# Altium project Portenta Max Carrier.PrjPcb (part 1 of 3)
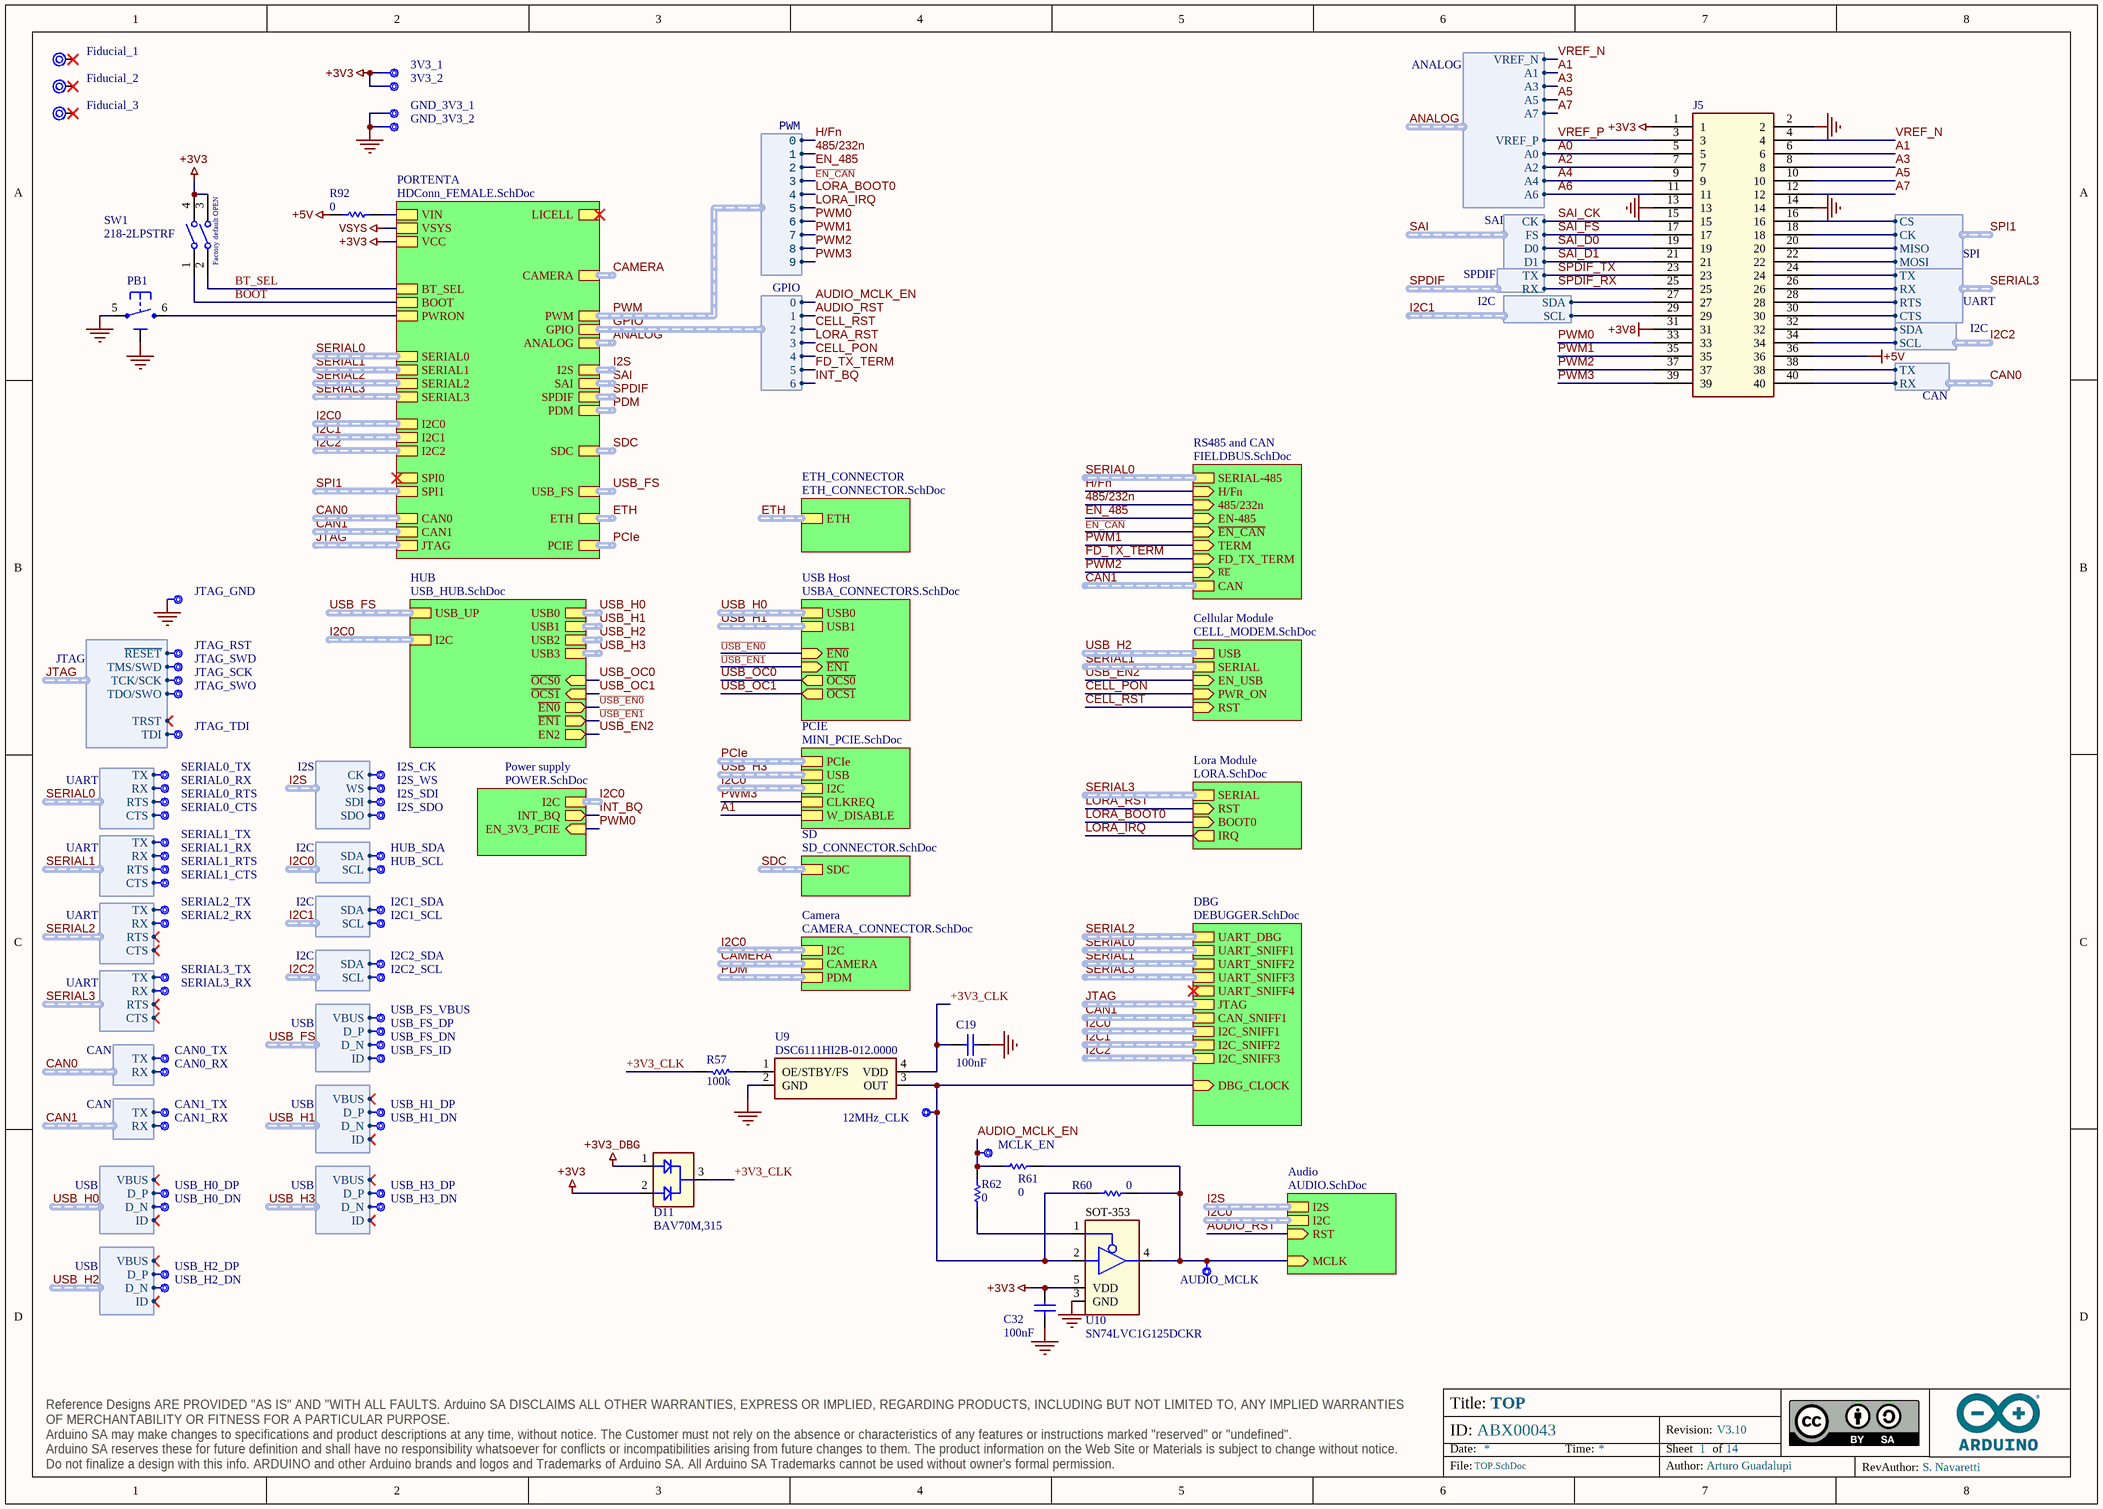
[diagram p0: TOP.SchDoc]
THICKNESS: 1.6mm; THD: X; TBD: _; TABS: X; SOLDERMASK_TOP: X; SOLDERMASK_PEELABLE_TOP: _; SOLDERMASK_PEELABLE_COLOR: _; SOLDERMASK_PEELABLE_BOTTOM: _; SOLDERMASK_COLOR: BLACK; SOLDERMASK_BOTTOM: X; SN/PB: _; SMD: X; SKU: ABX00043; SILK_TOP: X; SILK_COLOR: WHITE; SILK_BOTTOM: X; SCORING: _; RIGID/FLEX: _; RIGID: X; Revision: V3.10; PRESSFIT: _; POLYMIDE: _; PCB_SIZE: 101.60 mm x 101.60 mm; PANEL_SIZE: 230.20 mm x 120.60 mm; PANEL_REQUESTED: _; PANEL_PROVIDED: X; PANEL_NO: _; N_FIGURES: 2; NLAYERS: 4; NI/AU: _; MIN_TRACK_WIDTH_OUTER: 0.15mm; MIN_TRACK_WIDTH_INNER: 0.15mm; MIN_INSULATION_OUTER: 0.15mm; MIN_INSULATION_INNER: 0.15mm; MILLING: X; IPCNA: X; IPC3: _; IPC2: _; IPC1: _; HOLE_TOP_BOTTOM: X; HAL_LF: _; HAL: _; FR4_HTG: _; FR4: X; FLEX: _; FINISH_TBD: _; ENIG: X; EDGE_PLATING: _; DRILLS_SOLDER_FILLING: X; DRILLS_SLOT: _; DRILLS_RESIN_FILLING: _; DRILLS_PRESSFIT: _; DRILLS_LASER: _; DRILLS_FULL: X; DRILLS_COPPER_FILLING: _; DRILLS_BURIED: _; DRILLS_BLIND: _; BGA: _; Author: Silvio Navaretti; ADJUSTMENTS: _
14 sheets, 504 parts. Net scope: hierarchical (ports join the sheet entries above them; power ports are global).
Board files: PCB.PcbDoc, Panel.PcbDoc
Sheets:
  TOP.SchDoc
    Power supply = POWER.SchDoc
    RS485 and CAN = FIELDBUS.SchDoc
    PORTENTA = HDConn_FEMALE.SchDoc
    Audio = AUDIO.SchDoc
    PCIE = MINI_PCIE.SchDoc
    SD = SD_CONNECTOR.SchDoc
    Cellular Module = CELL_MODEM.SchDoc
    HUB = USB_HUB.SchDoc
    USB Host = USBA_CONNECTORS.SchDoc
    Camera = CAMERA_CONNECTOR.SchDoc
    Lora Module = LORA.SchDoc
    DBG = DEBUGGER.SchDoc
    ETH_CONNECTOR = ETH_CONNECTOR.SchDoc

## Sheet TOP.SchDoc: TOP
size A3; Author: Arturo Guadalupi; CompanyName: Arduino srl; DocumentNumber: ABX00043; Revision: V3.10; SheetNumber: 1; SheetTotal: 14; RevAuthor: S. Navaretti; Number: HWECB-42

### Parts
3V3_1  CMP-018-0005-A.3  [TP-1.00MM]  (value not drawn)  (no BOM)
3V3_2  CMP-018-0005-A.3  [TP-1.00MM]  (value not drawn)  (no BOM)
12MHz_CLK  CMP-018-0005-A.3  [TP-1.00MM]  (value not drawn)  (no BOM)
AUDIO_MCLK  CMP-018-0005-A.3  [TP-1.00MM]  (value not drawn)  (no BOM)
C19  value 100nF  [CAP-0402]  (hidden comment: C0402C104K4RACTU)
C32  value 100nF  [CAP-0402]  (hidden comment: C0402C104K4RACTU)
CAN0_RX  CMP-018-0005-A.3  [TP-1.00MM]  (value not drawn)  (no BOM)
CAN0_TX  CMP-018-0005-A.3  [TP-1.00MM]  (value not drawn)  (no BOM)
CAN1_RX  CMP-018-0005-A.3  [TP-1.00MM]  (value not drawn)  (no BOM)
CAN1_TX  CMP-018-0005-A.3  [TP-1.00MM]  (value not drawn)  (no BOM)
D11  BAV70M,315  [SOT883]
Fiducial_1  Fiducial mark 1mm with 2mm solder  [Fiducial mark 1mm with circle-Footprint-1]  (value not drawn)  (no BOM)
Fiducial_2  Fiducial mark 1mm with 2mm solder  [Fiducial mark 1mm with circle-Footprint-1]  (value not drawn)  (no BOM)
Fiducial_3  Fiducial mark 1mm with 2mm solder  [Fiducial mark 1mm with circle-Footprint-1]  (value not drawn)  (no BOM)
GND_3V3_1  CMP-018-0005-A.3  [TP-1.00MM]  (value not drawn)  (no BOM)
GND_3V3_2  CMP-018-0005-A.3  [TP-1.00MM]  (value not drawn)  (no BOM)
HUB_SCL  CMP-018-0005-A.3  [TP-1.00MM]  (value not drawn)  (no BOM)
HUB_SDA  CMP-018-0005-A.3  [TP-1.00MM]  (value not drawn)  (no BOM)
I2C1_SCL  CMP-018-0005-A.3  [TP-1.00MM]  (value not drawn)  (no BOM)
I2C1_SDA  CMP-018-0005-A.3  [TP-1.00MM]  (value not drawn)  (no BOM)
I2C2_SCL  CMP-018-0005-A.3  [TP-1.00MM]  (value not drawn)  (no BOM)
I2C2_SDA  CMP-018-0005-A.3  [TP-1.00MM]  (value not drawn)  (no BOM)
I2S_CK  CMP-018-0005-A.3  [TP-1.00MM]  (value not drawn)  (no BOM)
I2S_SDI  CMP-018-0005-A.3  [TP-1.00MM]  (value not drawn)  (no BOM)
I2S_SDO  CMP-018-0005-A.3  [TP-1.00MM]  (value not drawn)  (no BOM)
I2S_WS  CMP-018-0005-A.3  [TP-1.00MM]  (value not drawn)  (no BOM)
J5  FW-20-05-G-D-254-150  [FW-20-05-G-D-254-150-Footprint-1]  (value not drawn)
JTAG_GND  CMP-018-0005-A.3  [TP-1.00MM]  (value not drawn)  (no BOM)
JTAG_RST  CMP-018-0005-A.3  [TP-1.00MM]  (value not drawn)  (no BOM)
JTAG_SCK  CMP-018-0005-A.3  [TP-1.00MM]  (value not drawn)  (no BOM)
JTAG_SWD  CMP-018-0005-A.3  [TP-1.00MM]  (value not drawn)  (no BOM)
JTAG_SWO  CMP-018-0005-A.3  [TP-1.00MM]  (value not drawn)  (no BOM)
JTAG_TDI  CMP-018-0005-A.3  [TP-1.00MM]  (value not drawn)  (no BOM)
MCLK_EN  CMP-018-0005-A.3  [TP-1.00MM]  (value not drawn)  (no BOM)
PB1  PTS820J25KSMTRLFS  [C&K_PTS820_NO_HOLES-1]  (value not drawn)
R57  value 100k  [RES-0402]  (hidden comment: CRCW0402100KFKEDC)
R60  value 0  [RES-0402]  (hidden comment: CRCW04020000Z0EDC)
R61  value 0  [RES-0402]  (hidden comment: CRCW04020000Z0EDC)
R62  value 0  [RES-0402]  (hidden comment: CRCW04020000Z0EDC)
R92  value 0  [RES-0805]  (hidden comment: CRCW08050000Z0EB)
SERIAL0_CTS  CMP-018-0005-A.3  [TP-1.00MM]  (value not drawn)  (no BOM)
SERIAL0_RTS  CMP-018-0005-A.3  [TP-1.00MM]  (value not drawn)  (no BOM)
SERIAL0_RX  CMP-018-0005-A.3  [TP-1.00MM]  (value not drawn)  (no BOM)
SERIAL0_TX  CMP-018-0005-A.3  [TP-1.00MM]  (value not drawn)  (no BOM)
SERIAL1_CTS  CMP-018-0005-A.3  [TP-1.00MM]  (value not drawn)  (no BOM)
SERIAL1_RTS  CMP-018-0005-A.3  [TP-1.00MM]  (value not drawn)  (no BOM)
SERIAL1_RX  CMP-018-0005-A.3  [TP-1.00MM]  (value not drawn)  (no BOM)
SERIAL1_TX  CMP-018-0005-A.3  [TP-1.00MM]  (value not drawn)  (no BOM)
SERIAL2_RX  CMP-018-0005-A.3  [TP-1.00MM]  (value not drawn)  (no BOM)
SERIAL2_TX  CMP-018-0005-A.3  [TP-1.00MM]  (value not drawn)  (no BOM)
SERIAL3_RX  CMP-018-0005-A.3  [TP-1.00MM]  (value not drawn)  (no BOM)
SERIAL3_TX  CMP-018-0005-A.3  [TP-1.00MM]  (value not drawn)  (no BOM)
SW1  218-2LPSTRF  [CTS-218-2LPST_V]
U9  DSC6111HI2B-012.0000  [DFN120P120X89-4M]
U10  SN74LVC1G125DCKR  [SC70-5]
USB_FS_DN  CMP-018-0005-A.3  [TP-1.00MM]  (value not drawn)  (no BOM)
USB_FS_DP  CMP-018-0005-A.3  [TP-1.00MM]  (value not drawn)  (no BOM)
USB_FS_ID  CMP-018-0005-A.3  [TP-1.00MM]  (value not drawn)  (no BOM)
USB_FS_VBUS  CMP-018-0005-A.3  [TP-1.00MM]  (value not drawn)  (no BOM)
USB_H0_DN  CMP-018-0005-A.3  [TP-1.00MM]  (value not drawn)  (no BOM)
USB_H0_DP  CMP-018-0005-A.3  [TP-1.00MM]  (value not drawn)  (no BOM)
USB_H1_DN  CMP-018-0005-A.3  [TP-1.00MM]  (value not drawn)  (no BOM)
USB_H1_DP  CMP-018-0005-A.3  [TP-1.00MM]  (value not drawn)  (no BOM)
USB_H2_DN  CMP-018-0005-A.3  [TP-1.00MM]  (value not drawn)  (no BOM)
USB_H2_DP  CMP-018-0005-A.3  [TP-1.00MM]  (value not drawn)  (no BOM)
USB_H3_DN  CMP-018-0005-A.3  [TP-1.00MM]  (value not drawn)  (no BOM)
USB_H3_DP  CMP-018-0005-A.3  [TP-1.00MM]  (value not drawn)  (no BOM)

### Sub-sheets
Audio = AUDIO.SchDoc: RST (in), I2C (harness I2C), I2S (harness I2S), MCLK (in)
Camera = CAMERA_CONNECTOR.SchDoc: CAMERA (harness CAMERA), I2C (harness I2C), PDM (harness PDM)
Cellular Module = CELL_MODEM.SchDoc: USB (harness USB), EN_USB (in), PWR_ON (in), RST (in), SERIAL (harness SERIAL)
DBG = DEBUGGER.SchDoc: JTAG (harness JTAG), UART_SNIFF4 (harness UART), UART_SNIFF2 (harness UART), UART_SNIFF3 (harness UART), UART_SNIFF1 (harness UART), CAN_SNIFF1 (harness CAN), I2C_SNIFF1 (harness I2C), I2C_SNIFF3 (harness I2C), I2C_SNIFF2 (harness I2C), UART_DBG (harness UART), DBG_CLOCK (in)
ETH_CONNECTOR = ETH_CONNECTOR.SchDoc: ETH (harness ETH)
HUB = USB_HUB.SchDoc: USB0 (harness USB), USB1 (harness USB), USB2 (harness USB), USB3 (harness USB), USB_UP (harness USB), I2C (harness I2C), ~{OCS1} (in), ~{OCS0} (in), ~{EN0} (out), ~{EN1} (out), EN2 (out)
Lora Module = LORA.SchDoc: RST (in), BOOT0 (in), IRQ (out), SERIAL (harness UART)
PCIE = MINI_PCIE.SchDoc: PCIe (harness PCIE), USB (harness USB), I2C (harness I2C), CLKREQ, W_DISABLE
PORTENTA = HDConn_FEMALE.SchDoc: PWRON, PWM (harness PWM), GPIO (harness GPIO), CAMERA (harness CAMERA), I2S (harness I2S), SERIAL0 (harness UART), SPDIF (harness SPDIF), CAN1 (harness CAN), PDM (harness PDM), I2C1 (harness I2C), CAN0 (harness CAN), SERIAL1 (harness UART), I2C0 (harness I2C), SDC (harness SDC), ETH (harness ETH), BT_SEL, SPI1 (harness SPI), SPI0 (harness SPI), SERIAL2 (harness UART), SERIAL3 (harness UART), SAI (harness SAI), BOOT, I2C2 (harness I2C), PCIE (harness PCIE), ANALOG (harness ANALOG), USB_FS (harness USB), JTAG (harness JTAG), VCC, LICELL, VIN, VSYS
Power supply = POWER.SchDoc: I2C (harness I2C), INT_BQ (out), EN_3V3_PCIE (in)
RS485 and CAN = FIELDBUS.SchDoc: H/Fn (in), 485/232n (in), SERIAL-485 (harness UART), EN-485 (in), CAN (harness CAN), ~{EN_CAN} (in), TERM (in), ~{RE} (in), FD_TX_TERM (in)
SD = SD_CONNECTOR.SchDoc: SDC (harness SDC)
USB Host = USBA_CONNECTORS.SchDoc: USB0 (harness USB), USB1 (harness USB), ~{EN0} (in), ~{EN1} (in), ~{OCS0} (out), ~{OCS}~{1} (out)

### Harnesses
PWM: 0, 1, 2, 3, 4, 5, 6, 7, 8, 9
ANALOG: VREF_P, A0, A1, A2, A3, A7, A6, A5, A4, VREF_N
GPIO: 0, 1, 2, 3, 4, 5, 6
I2C: SCL, SDA
CAN: RX, TX
SPI: CS, CK, MISO, MOSI
SAI: CK, FS, D0, D1
UART: CTS, RTS, RX, TX
SPDIF: RX, TX
UART: RX, TX, RTS, CTS
I2S: CK, SDI, SDO, WS
I2C: SDA, SCL
USB: VBUS, D_P, D_N, ID
JTAG: ~{RESET}, TCK/SCK, TDI, TDO/SWO, TMS/SWD, TRST

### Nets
+3V3: 3V3_1.X 3V3_2.X C32.1 D11.2(A2) J5.1 SW1.3 SW1.4 U10.5(VDD) ; sheet PORTENTA/VCC
+3V3_DBG: D11.1(A1)
+3V8: J5.31
+5V: J5.36 R92.1
GND: C19.1 C32.2 GND_3V3_1.X GND_3V3_2.X J5.2 J5.13 J5.14 JTAG_GND.X PB1.5 PB1.PAD U9.2(GND) U10.3(GND)
485/232n: sheet RS485 and CAN/485/232n, sheet PORTENTA/PWM.1
+3V3_CLK: C19.2 D11.3(K) R57.2 U9.4(VDD)  [project net +3V3_CLK_1]
A0: J5.5 ; sheet PORTENTA/ANALOG.A0
A1: J5.6 ; sheet PCIE/W_DISABLE, sheet PORTENTA/ANALOG.A1
A2: J5.7 ; sheet PORTENTA/ANALOG.A2
A3: J5.8 ; sheet PORTENTA/ANALOG.A3
A4: J5.9 ; sheet PORTENTA/ANALOG.A4
A5: J5.10 ; sheet PORTENTA/ANALOG.A5
A6: J5.11 ; sheet PORTENTA/ANALOG.A6
A7: J5.12 ; sheet PORTENTA/ANALOG.A7
AUDIO_MCLK_EN: MCLK_EN.X R61.1 R62.2 ; sheet PORTENTA/GPIO.0
AUDIO_RST: sheet Audio/RST, sheet PORTENTA/GPIO.1
BOOT: SW1.1 ; sheet PORTENTA/BOOT
BT_SEL: SW1.2 ; sheet PORTENTA/BT_SEL
CAN0.RX: CAN0_RX.X J5.40 ; sheet PORTENTA/CAN0.RX
CAN0.TX: CAN0_TX.X J5.38 ; sheet PORTENTA/CAN0.TX
CAN1.RX: CAN1_RX.X ; sheet RS485 and CAN/CAN.RX
CAN1.TX: CAN1_TX.X ; sheet RS485 and CAN/CAN.TX
CELL_PON: sheet Cellular Module/PWR_ON, sheet PORTENTA/GPIO.4
CELL_RST: sheet Cellular Module/RST, sheet PORTENTA/GPIO.2
~{EN_CAN}: sheet RS485 and CAN/~{EN_CAN}, sheet PORTENTA/PWM.3
EN_485: sheet RS485 and CAN/EN-485, sheet PORTENTA/PWM.2
FD_TX_TERM: sheet RS485 and CAN/FD_TX_TERM, sheet PORTENTA/GPIO.5
H/Fn: sheet RS485 and CAN/H/Fn, sheet PORTENTA/PWM.0
I2C0.SCL: HUB_SCL.X ; sheet Power supply/I2C.SCL
I2C0.SDA: HUB_SDA.X ; sheet Power supply/I2C.SDA
I2C1.SCL: I2C1_SCL.X J5.29 ; sheet PORTENTA/I2C1.SCL
I2C1.SDA: I2C1_SDA.X J5.27 ; sheet PORTENTA/I2C1.SDA
I2C2.SCL: I2C2_SCL.X J5.34 ; sheet PORTENTA/I2C2.SCL
I2C2.SDA: I2C2_SDA.X J5.32 ; sheet PORTENTA/I2C2.SDA
I2S.CK: I2S_CK.X ; sheet PORTENTA/I2S.CK
I2S.SDI: I2S_SDI.X ; sheet PORTENTA/I2S.SDI
I2S.SDO: I2S_SDO.X ; sheet PORTENTA/I2S.SDO
I2S.WS: I2S_WS.X ; sheet PORTENTA/I2S.WS
INT_BQ: sheet Power supply/INT_BQ, sheet PORTENTA/GPIO.6  [project net GPIO.6]
JTAG.~{RESET}: JTAG_RST.X ; sheet PORTENTA/JTAG.~{RESET}
JTAG.TCK/SCK: JTAG_SCK.X ; sheet PORTENTA/JTAG.TCK/SCK
JTAG.TDI: JTAG_TDI.X ; sheet PORTENTA/JTAG.TDI
JTAG.TDO/SWO: JTAG_SWO.X ; sheet PORTENTA/JTAG.TDO/SWO
JTAG.TMS/SWD: JTAG_SWD.X ; sheet PORTENTA/JTAG.TMS/SWD
LORA_BOOT0: sheet Lora Module/BOOT0, sheet PORTENTA/PWM.4
LORA_IRQ: sheet Lora Module/IRQ, sheet PORTENTA/PWM.5
LORA_RST: sheet Lora Module/RST, sheet PORTENTA/GPIO.3  [project net GPIO.3]
PWM0: J5.33 ; sheet Power supply/EN_3V3_PCIE, sheet PORTENTA/PWM.6  [project net PWM.6]
PWM1: J5.35 ; sheet RS485 and CAN/TERM, sheet PORTENTA/PWM.7  [project net PWM.7]
PWM2: J5.37 ; sheet RS485 and CAN/~{RE}, sheet PORTENTA/PWM.8  [project net PWM.8]
PWM3: J5.39 ; sheet PCIE/CLKREQ, sheet PORTENTA/PWM.9  [project net PWM.9]
SAI_CK: J5.15 ; sheet PORTENTA/SAI.CK  [project net SAI.CK]
SAI_D0: J5.19 ; sheet PORTENTA/SAI.D0  [project net SAI.D0]
SAI_D1: J5.21 ; sheet PORTENTA/SAI.D1  [project net SAI.D1]
SAI_FS: J5.17 ; sheet PORTENTA/SAI.FS  [project net SAI.FS]
SERIAL0.CTS: SERIAL0_CTS.X ; sheet RS485 and CAN/SERIAL-485.CTS
SERIAL0.RTS: SERIAL0_RTS.X ; sheet RS485 and CAN/SERIAL-485.RTS
SERIAL0.RX: SERIAL0_RX.X ; sheet RS485 and CAN/SERIAL-485.RX
SERIAL0.TX: SERIAL0_TX.X ; sheet RS485 and CAN/SERIAL-485.TX
SERIAL1.CTS: SERIAL1_CTS.X ; sheet PORTENTA/SERIAL1.CTS
SERIAL1.RTS: SERIAL1_RTS.X ; sheet PORTENTA/SERIAL1.RTS
SERIAL1.RX: SERIAL1_RX.X ; sheet PORTENTA/SERIAL1.RX
SERIAL1.TX: SERIAL1_TX.X ; sheet PORTENTA/SERIAL1.TX
SERIAL2.RX: SERIAL2_RX.X ; sheet PORTENTA/SERIAL2.RX
SERIAL2.TX: SERIAL2_TX.X ; sheet PORTENTA/SERIAL2.TX
SERIAL3.CTS: J5.30 ; sheet PORTENTA/SERIAL3.CTS
SERIAL3.RTS: J5.28 ; sheet PORTENTA/SERIAL3.RTS
SERIAL3.RX: J5.26 SERIAL3_RX.X ; sheet PORTENTA/SERIAL3.RX
SERIAL3.TX: J5.24 SERIAL3_TX.X ; sheet PORTENTA/SERIAL3.TX
SPDIF_RX: J5.25 ; sheet PORTENTA/SPDIF.RX  [project net SPDIF.RX]
SPDIF_TX: J5.23 ; sheet PORTENTA/SPDIF.TX  [project net SPDIF.TX]
SPI1.CK: J5.18 ; sheet PORTENTA/SPI1.CK
SPI1.CS: J5.16 ; sheet PORTENTA/SPI1.CS
SPI1.MISO: J5.20 ; sheet PORTENTA/SPI1.MISO
SPI1.MOSI: J5.22 ; sheet PORTENTA/SPI1.MOSI
~{USB_EN0}: sheet HUB/~{EN0}, sheet USB Host/~{EN0}
~{USB_EN1}: sheet HUB/~{EN1}, sheet USB Host/~{EN1}
USB_EN2: sheet Cellular Module/EN_USB, sheet HUB/EN2
USB_FS.D_N: USB_FS_DN.X ; sheet PORTENTA/USB_FS.D_N
USB_FS.D_P: USB_FS_DP.X ; sheet PORTENTA/USB_FS.D_P
USB_FS.ID: USB_FS_ID.X ; sheet PORTENTA/USB_FS.ID
USB_FS.VBUS: USB_FS_VBUS.X ; sheet PORTENTA/USB_FS.VBUS
USB_H0.D_N: USB_H0_DN.X ; sheet HUB/USB0.D_N
USB_H0.D_P: USB_H0_DP.X ; sheet HUB/USB0.D_P
USB_H1.D_N: USB_H1_DN.X ; sheet HUB/USB1.D_N
USB_H1.D_P: USB_H1_DP.X ; sheet HUB/USB1.D_P
USB_H2.D_N: USB_H2_DN.X ; sheet Cellular Module/USB.D_N
USB_H2.D_P: USB_H2_DP.X ; sheet Cellular Module/USB.D_P
USB_H3.D_N: USB_H3_DN.X ; sheet PCIE/USB.D_N
USB_H3.D_P: USB_H3_DP.X ; sheet PCIE/USB.D_P
USB_OC0: sheet HUB/~{OCS0}, sheet USB Host/~{OCS0}
USB_OC1: sheet HUB/~{OCS1}, sheet USB Host/~{OCS}~{1}
VIN: R92.2 ; sheet PORTENTA/VIN
VREF_N: J5.4 ; sheet PORTENTA/ANALOG.VREF_N  [project net ANALOG.VREF_N]
VREF_P: J5.3 ; sheet PORTENTA/ANALOG.VREF_P  [project net ANALOG.VREF_P]
Net12MHz_CLK_X: 12MHz_CLK.X R60.1 U9.3(OUT) U10.2(IN) ; sheet DBG/DBG_CLOCK
NetAUDIO_MCLK_X: AUDIO_MCLK.X R60.2 R61.2 U10.4(OUT) ; sheet Audio/MCLK
NetJ2_5: PB1.6 ; sheet PORTENTA/PWRON
NetR57_1: R57.1 U9.1(OE/STBY/FS)
NetR62_1: R62.1 U10.1(~{OE})

Not connected (* = marked no-connect by the designer): Fiducial_1 1*; Fiducial_2 1*; Fiducial_3 1*

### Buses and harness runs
harness ANALOG = sheet PORTENTA/ANALOG
harness CAMERA = sheet Camera/CAMERA
harness CAMERA = sheet PORTENTA/CAMERA
harness CAN0 = sheet PORTENTA/CAN0
harness CAN1 = sheet DBG/CAN_SNIFF1
harness CAN1 = sheet PORTENTA/CAN1
harness CAN1 = sheet RS485 and CAN/CAN
harness ETH = sheet ETH_CONNECTOR/ETH
harness ETH = sheet PORTENTA/ETH
harness GPIO = sheet PORTENTA/GPIO
harness I2C0 = sheet Audio/I2C
harness I2C0 = sheet Camera/I2C
harness I2C0 = sheet DBG/I2C_SNIFF1
harness I2C0 = sheet HUB/I2C
harness I2C0 = sheet PCIE/I2C
harness I2C0 = sheet PORTENTA/I2C0
harness I2C0 = sheet Power supply/I2C
harness I2C1 = sheet DBG/I2C_SNIFF2
harness I2C1 = sheet PORTENTA/I2C1
harness I2C2 = sheet DBG/I2C_SNIFF3
harness I2C2 = sheet PORTENTA/I2C2
harness I2S = sheet Audio/I2S
harness I2S = sheet PORTENTA/I2S
harness JTAG = sheet DBG/JTAG
harness JTAG = sheet PORTENTA/JTAG
harness PCIe = sheet PCIE/PCIe
harness PCIe = sheet PORTENTA/PCIE
harness PDM = sheet Camera/PDM
harness PDM = sheet PORTENTA/PDM
harness PWM = sheet PORTENTA/PWM
harness SAI = sheet PORTENTA/SAI
harness SDC = sheet PORTENTA/SDC
harness SDC = sheet SD/SDC
harness SERIAL0 = sheet DBG/UART_SNIFF1
harness SERIAL0 = sheet PORTENTA/SERIAL0
harness SERIAL0 = sheet RS485 and CAN/SERIAL-485
harness SERIAL1 = sheet Cellular Module/SERIAL
harness SERIAL1 = sheet DBG/UART_SNIFF2
harness SERIAL1 = sheet PORTENTA/SERIAL1
harness SERIAL2 = sheet DBG/UART_DBG
harness SERIAL2 = sheet PORTENTA/SERIAL2
harness SERIAL3 = sheet DBG/UART_SNIFF3
harness SERIAL3 = sheet Lora Module/SERIAL
harness SERIAL3 = sheet PORTENTA/SERIAL3
harness SPDIF = sheet PORTENTA/SPDIF
harness SPI1 = sheet PORTENTA/SPI1
harness USB_FS = sheet HUB/USB_UP
harness USB_FS = sheet PORTENTA/USB_FS
harness USB_H0 = sheet HUB/USB0
harness USB_H0 = sheet USB Host/USB0
harness USB_H1 = sheet HUB/USB1
harness USB_H1 = sheet USB Host/USB1
harness USB_H2 = sheet Cellular Module/USB
harness USB_H2 = sheet HUB/USB2
harness USB_H3 = sheet HUB/USB3
harness USB_H3 = sheet PCIE/USB

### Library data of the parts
3V3_1 3V3_2 12MHz_CLK AUDIO_MCLK CAN0_RX CAN0_TX CAN1_RX CAN1_TX GND_3V3_1 GND_3V3_2 HUB_SCL HUB_SDA I2C1_SCL I2C1_SDA I2C2_SCL I2C2_SDA I2S_CK I2S_SDI I2S_SDO I2S_WS JTAG_GND JTAG_RST JTAG_SCK JTAG_SWD JTAG_SWO JTAG_TDI MCLK_EN SERIAL0_CTS SERIAL0_RTS SERIAL0_RX SERIAL0_TX SERIAL1_CTS SERIAL1_RTS SERIAL1_RX SERIAL1_TX SERIAL2_RX SERIAL2_TX USB_FS_DN USB_FS_DP USB_FS_ID USB_FS_VBUS USB_H0_DN USB_H0_DP USB_H1_DN USB_H1_DP USB_H2_DN USB_H2_DP USB_H3_DN USB_H3_DP = UT0013-A.2: Test point 1.00mm
C19 C32 = C0012-A.9: CAP CHIP 0402 100nF 16V X7R 10%; Manufacturer: KEMET; Code Arduino: 0132
D11 = D0050-A.2: DIODE ARRAY GP 100V 150MA SOT883; Manufacturer: Nexperia; Device Type: Diode dual; Code Arduino: D0050
Fiducial_1-Fiducial_3 = UT0024-A.6
J5 = J0031-A.3: CONN BOARD STACKER HDR 40 POS 1.27mm ST SMD; Manufacturer: Samtec; Gender: Male; Number of Contacts: 40; Code Arduino: J0031
PB1 = B0006-A.6: PUSHBUTTON SMD PTS820 NO HOLES; Manufacturer: C&K; Code Arduino: A5506; Actuator Type: Standard; Mechanical Life: 100000Cycles
R57 = R0001-A.5: RES CHIP 0402 100K 1% 1/16W; Manufacturer: Vishay; Power: 63mW; Code Arduino: 0134
R60-R62 = R0000-A.5: RES CHIP 0402 0R 1/16W; Manufacturer: Vishay; Code Arduino: 0039; Tolerance: J; Power: 63mW
R92 = R0131-A.3: RES CHIP 0805 0R 1/8W; Manufacturer: Vishay; Code Arduino: A5394; Power: 125mW; Tolerance: J
SERIAL3_RX SERIAL3_TX = UT0013-A.1: Test point 1.00mm
SW1 = S0022-A.1: SWITCH DIP NORMALLY OPEN; Manufacturer: CTS Corporation; Number of Positions: 2; Actuator Type: Slide (Standard); Washable: Yes; Pitch: 0.05inch; Electrical Life: 1000Cycles; Current Rating: 25mA; Code Arduino: S0022; Voltage Rating (DC): 24V; Throw Configuration: SPST; Contact Resistance: 100mR
U9 = X0013-A.3: MEMS OSC 12MHz VDD 1.7V to 3.6V VFLGA 1.6mm x 1.2mm; Manufacturer: Microchip; Code Arduino: X0013
U10 = U0083-A.6: IC BUS.BUFFER GATE   SC70-5 (SOT353); Manufacturer: Texas Instruments; Code Arduino: 0040

## Sheet POWER.SchDoc: POWER
size A3; Author: Arturo Guadalupi; CompanyName: Arduino srl; DocumentNumber: ABX00043; Revision: V3.10; SheetNumber: 12; SheetTotal: 14; RevAuthor: S. Navaretti
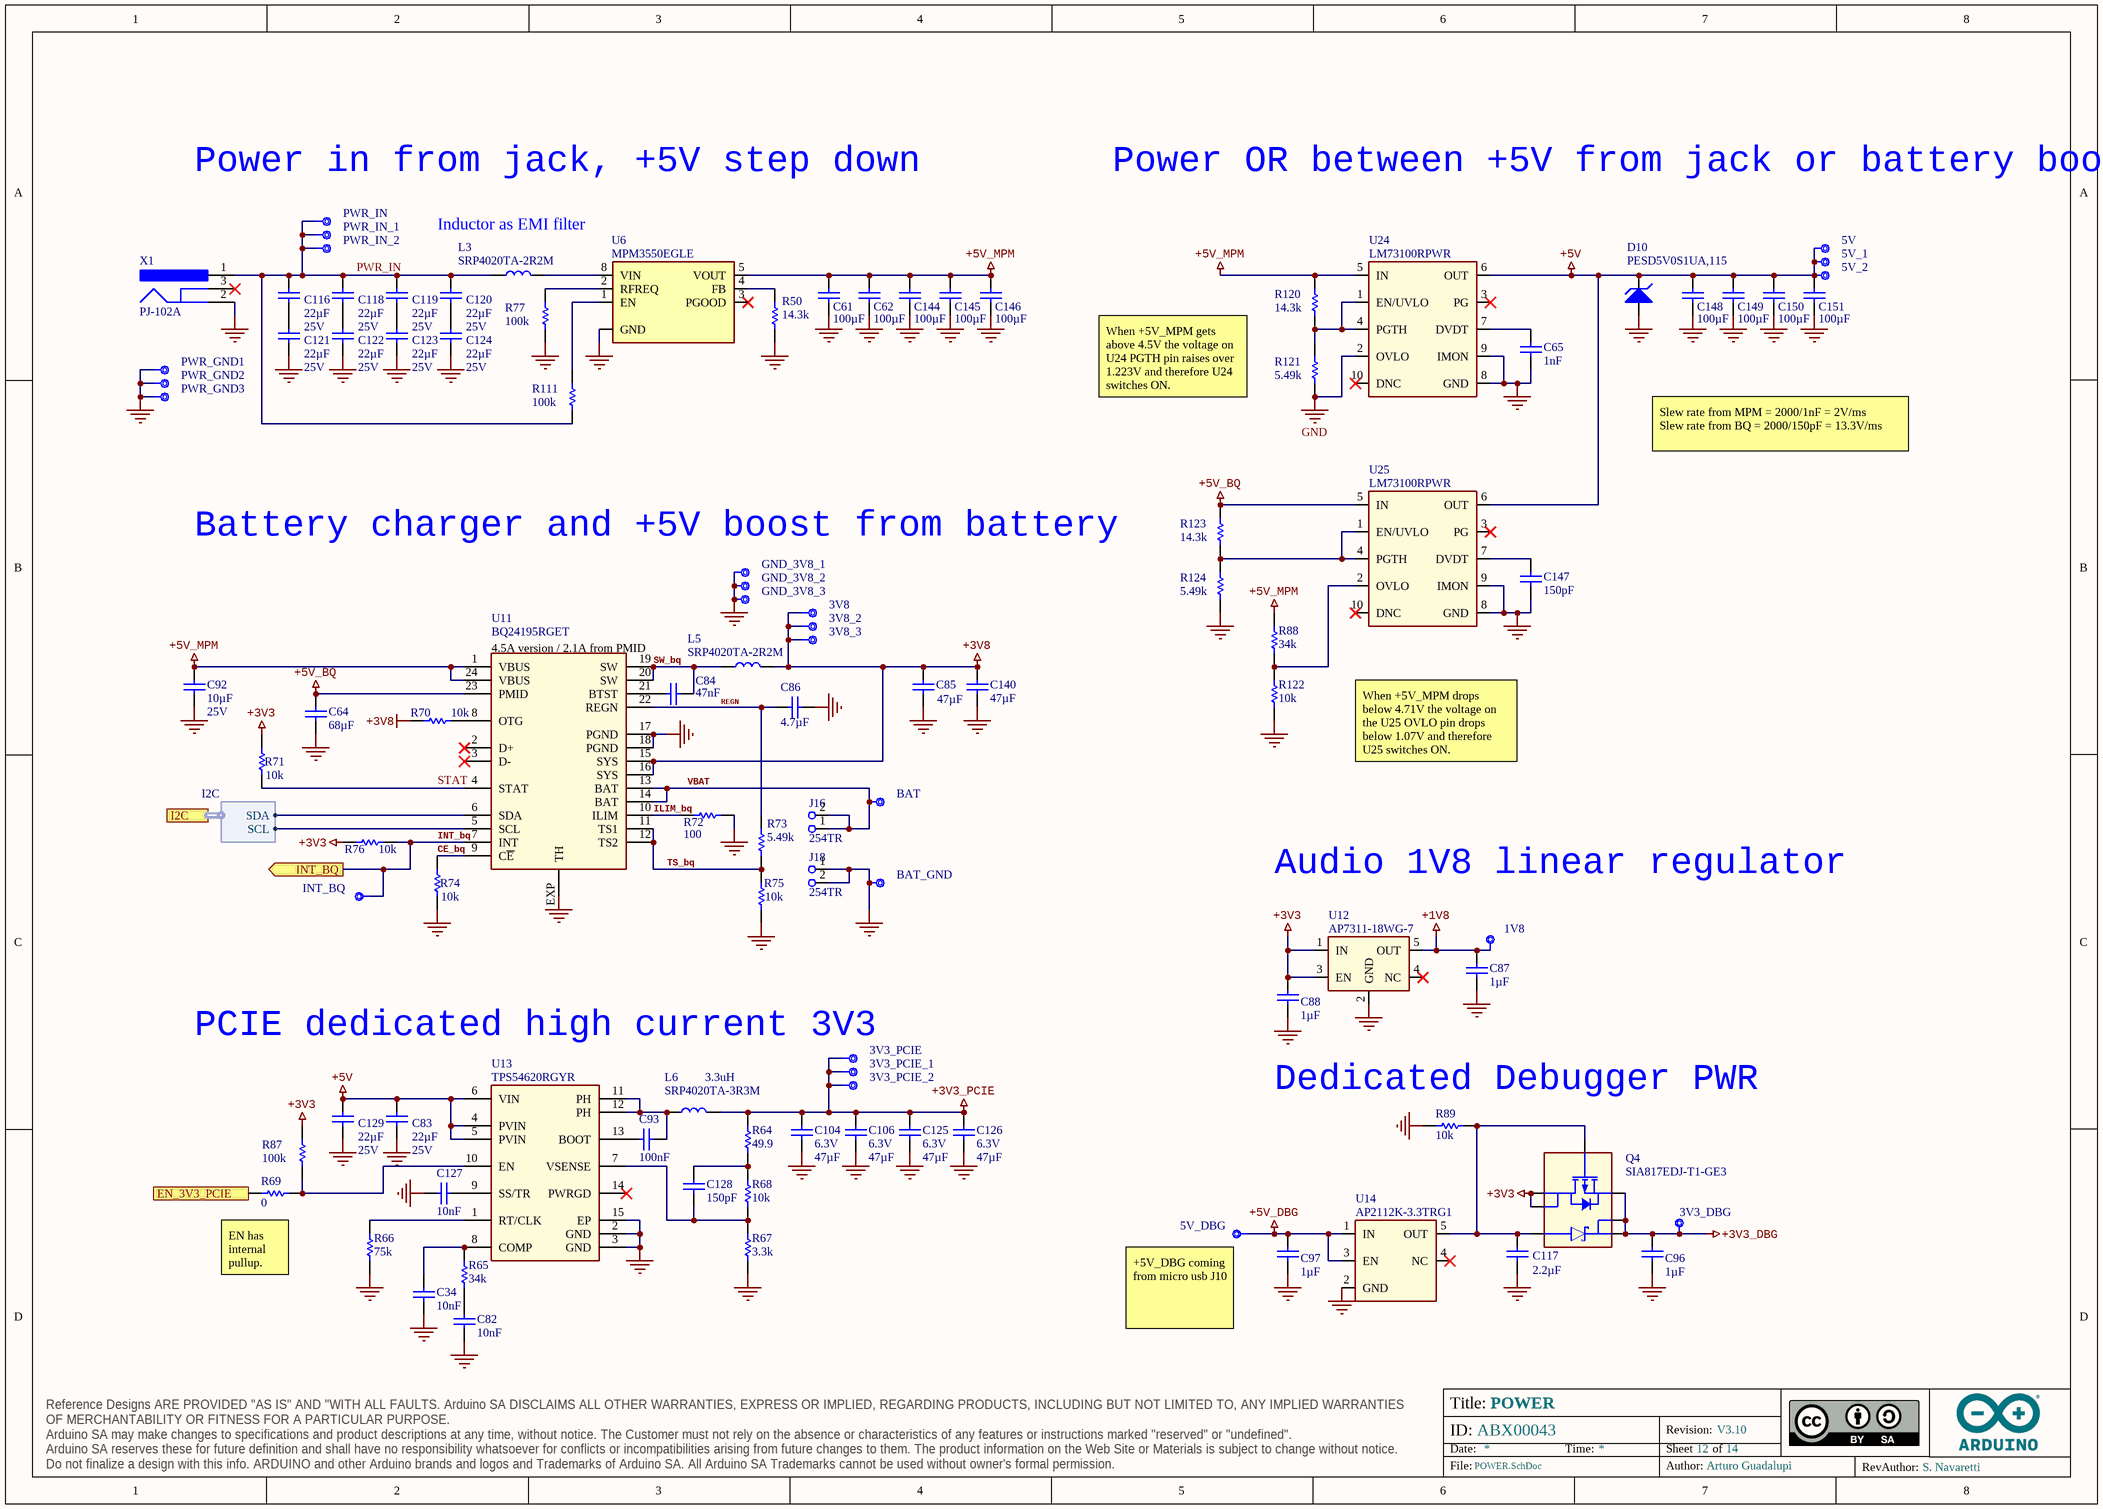
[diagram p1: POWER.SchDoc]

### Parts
1V8  CMP-018-0005-A.3  [TP-1.00MM]  (value not drawn)  (no BOM)
3V3_DBG  CMP-018-0005-A.3  [TP-1.00MM]  (value not drawn)  (no BOM)
3V3_PCIE  CMP-018-0005-A.3  [TP-1.00MM]  (value not drawn)  (no BOM)
3V3_PCIE_1  CMP-018-0005-A.3  [TP-1.00MM]  (value not drawn)  (no BOM)
3V3_PCIE_2  CMP-018-0005-A.3  [TP-1.00MM]  (value not drawn)  (no BOM)
3V8  CMP-018-0005-A.3  [TP-1.00MM]  (value not drawn)  (no BOM)
3V8_2  CMP-018-0005-A.3  [TP-1.00MM]  (value not drawn)  (no BOM)
3V8_3  CMP-018-0005-A.3  [TP-1.00MM]  (value not drawn)  (no BOM)
5V  CMP-018-0005-A.3  [TP-1.00MM]  (value not drawn)  (no BOM)
5V_1  CMP-018-0005-A.3  [TP-1.00MM]  (value not drawn)  (no BOM)
5V_2  CMP-018-0005-A.3  [TP-1.00MM]  (value not drawn)  (no BOM)
5V_DBG  CMP-018-0005-A.3  [TP-1.00MM]  (value not drawn)  (no BOM)
BAT  CMP-018-0005-A.3  [TP-1.00MM]  (value not drawn)  (no BOM)
BAT_GND  CMP-018-0005-A.3  [TP-1.00MM]  (value not drawn)  (no BOM)
C34  value 10nF  [CAP-0402]  (hidden comment: C0402C103K5RACTU)
C61  value 100µF  [CAP-1206]  (hidden comment: CL31A107MPHNNNE)
C62  value 100µF  [CAP-1206]  (hidden comment: CL31A107MPHNNNE)
C64  value 68µF  [CAP-1206]  (hidden comment: C3216X5R1A686M160AC)
C65  value 1nF  [CAP-0402]  (hidden comment: C0402C100K5RACTU)
C82  value 10nF  [CAP-0402]  (hidden comment: C0402C103K5RACTU)
C83  value 22µF  Voltage: 25V  [CAP-0805]  (hidden comment: CL21A226MAQNNNE)
C84  value 47nF  [CAP-0402]  (hidden comment: GRM155R61H473KE14D)
C85  value 47µF  [CAP-0603]  (hidden comment: ZRB18AR60J476ME01L)
C86  value 4.7µF  [CAP-0402]  (hidden comment: GRM155R60J475ME47D)
C87  value 1µF  [CAP-0402]  (hidden comment: C0402C105K8PACTU)
C88  value 1µF  [CAP-0402]  (hidden comment: C0402C105K8PACTU)
C92  value 10µF  Voltage: 25V  [CAP-0603]  (hidden comment: GRM188R61E106MA73J)
C93  value 100nF  [CAP-0402]  (hidden comment: C0402C104K4RACTU)
C96  value 1µF  [CAP-0402]  (hidden comment: C0402C105K8PACTU)
C97  value 1µF  [CAP-0402]  (hidden comment: C0402C105K8PACTU)
C104  value 47µF  Voltage Rating: 6.3V  [CAP-0603]  (hidden comment: ZRB18AR60J476ME01L)
C106  value 47µF  Voltage Rating: 6.3V  [CAP-0603]  (hidden comment: ZRB18AR60J476ME01L)
C116  value 22µF  Voltage: 25V  [CAP-0805]  (hidden comment: CL21A226MAQNNNE)
C117  value 2.2µF  [CAP-0402]  (hidden comment: GRM155R60J225KE95D)
C118  value 22µF  Voltage: 25V  [CAP-0805]  (hidden comment: CL21A226MAQNNNE)
C119  value 22µF  Voltage: 25V  [CAP-0805]  (hidden comment: CL21A226MAQNNNE)
C120  value 22µF  Voltage: 25V  [CAP-0805]  (hidden comment: CL21A226MAQNNNE)
C121  value 22µF  Voltage: 25V  [CAP-0805]  (hidden comment: CL21A226MAQNNNE)
C122  value 22µF  Voltage: 25V  [CAP-0805]  (hidden comment: CL21A226MAQNNNE)
C123  value 22µF  Voltage: 25V  [CAP-0805]  (hidden comment: CL21A226MAQNNNE)
C124  value 22µF  Voltage: 25V  [CAP-0805]  (hidden comment: CL21A226MAQNNNE)
C125  value 47µF  Voltage Rating: 6.3V  [CAP-0603]  (hidden comment: ZRB18AR60J476ME01L)
C126  value 47µF  Voltage Rating: 6.3V  [CAP-0603]  (hidden comment: ZRB18AR60J476ME01L)
C127  value 10nF  [CAP-0402]  (hidden comment: C0402C103K5RACTU)
C128  value 150pF  [CAP-0402]  (hidden comment: GRM1555C1H151FA01D)
C129  value 22µF  Voltage: 25V  [CAP-0805]  (hidden comment: CL21A226MAQNNNE)
C140  value 47µF  [CAP-0603]  (hidden comment: ZRB18AR60J476ME01L)
C144  value 100µF  [CAP-1206]  (hidden comment: CL31A107MPHNNNE)
C145  value 100µF  [CAP-1206]  (hidden comment: CL31A107MPHNNNE)
C146  value 100µF  [CAP-1206]  (hidden comment: CL31A107MPHNNNE)
C147  value 150pF  [CAP-0402]  (hidden comment: GRM1555C1H151FA01D)
C148  value 100µF  [CAP-1206]  (hidden comment: CL31A107MPHNNNE)
C149  value 100µF  [CAP-1206]  (hidden comment: CL31A107MPHNNNE)
C150  value 100µF  [CAP-1206]  (hidden comment: CL31A107MPHNNNE)
C151  value 100µF  [CAP-1206]  (hidden comment: CL31A107MPHNNNE)
D10  PESD5V0S1UA,115  [SOD323]
GND_3V8_1  CMP-018-0005-A.3  [TP-1.00MM]  (value not drawn)  (no BOM)
GND_3V8_2  CMP-018-0005-A.3  [TP-1.00MM]  (value not drawn)  (no BOM)
GND_3V8_3  CMP-018-0005-A.3  [TP-1.00MM]  (value not drawn)  (no BOM)
INT_BQ  CMP-018-0005-A.3  [TP-1.00MM]  (value not drawn)  (no BOM)
J16  254TR  [254TR-Footprint-1]
J18  254TR  [254TR-Footprint-1]
L3  SRP4020TA-2R2M  [SRP4020]
L5  SRP4020TA-2R2M  [SRP4020]
L6  SRP4020TA-3R3M  value 3.3uH  [SRP4020]
PWR_GND1  CMP-018-0005-A.3  [TP-1.00MM]  (value not drawn)  (no BOM)
PWR_GND2  CMP-018-0005-A.3  [TP-1.00MM]  (value not drawn)  (no BOM)
PWR_GND3  CMP-018-0005-A.3  [TP-1.00MM]  (value not drawn)  (no BOM)
PWR_IN  CMP-018-0005-A.3  [TP-1.00MM]  (value not drawn)  (no BOM)
PWR_IN_1  CMP-018-0005-A.3  [TP-1.00MM]  (value not drawn)  (no BOM)
PWR_IN_2  CMP-018-0005-A.3  [TP-1.00MM]  (value not drawn)  (no BOM)
Q4  SIA817EDJ-T1-GE3  [SON65P205X205X75-8N-MWSD]
R50  value 14.3k  [RES-0402]  (hidden comment: CRCW040214K3FKED)
R64  value 49.9  [RES-0402]  (hidden comment: CRCW040249R9FKEDHP)
R65  value 34k  [RES-0402]  (hidden comment: RC0402FR-0734KL)
R66  value 75k  [RES-0402]  (hidden comment: CRCW040275K0FKED)
R67  value 3.3k  [RES-0402]  (hidden comment: RC0402FR-073K3L)
R68  value 10k  [RES-0402]  (hidden comment: CRCW040210K0FKED)
R69  value 0  [RES-0402]  (hidden comment: CRCW04020000Z0EDC)
R70  value 10k  [RES-0402]  (hidden comment: CRCW040210K0FKED)
R71  value 10k  [RES-0402]  (hidden comment: CRCW040210K0FKED)
R72  value 100  [RES-0402]  (hidden comment: CRCW0402100RFKED)
R73  value 5.49k  [RES-0402]  (hidden comment: CRCW04025K49FKED)
R74  value 10k  [RES-0402]  (hidden comment: CRCW040210K0FKED)
R75  value 10k  [RES-0402]  (hidden comment: CRCW040210K0FKED)
R76  value 10k  [RES-0402]  (hidden comment: CRCW040210K0FKED)
R77  value 100k  [RES-0402]  (hidden comment: CRCW0402100KFKEDC)
R87  value 100k  [RES-0402]  (hidden comment: CRCW0402100KFKEDC)
R88  value 34k  [RES-0402]  (hidden comment: RC0402FR-0734KL)
R89  value 10k  [RES-0402]  (hidden comment: CRCW040210K0FKED)
R111  value 100k  [RES-0402]  (hidden comment: CRCW0402100KFKEDC)
R120  value 14.3k  [RES-0402]  (hidden comment: CRCW040214K3FKED)
R121  value 5.49k  [RES-0402]  (hidden comment: CRCW04025K49FKED)
R122  value 10k  [RES-0402]  (hidden comment: CRCW040210K0FKED)
R123  value 14.3k  [RES-0402]  (hidden comment: CRCW040214K3FKED)
R124  value 5.49k  [RES-0402]  (hidden comment: CRCW04025K49FKED)
U6  MPM3550EGLE  [LGA18C100P6X4_1200X1200X360]
U11  BQ24195RGET  [VQFN24]
U12  AP7311-18WG-7  [SOT25]
U13  TPS54620RGYR  [RHL0014A_V]
U14  AP2112K-3.3TRG1  [SOT25]
U24  LM73100RPWR  [QFN50P200X200X100-16N]
U25  LM73100RPWR  [QFN50P200X200X100-16N]
X1  PJ-102A  [CUI-PJ-102A_V]

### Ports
EN_3V3_PCIE (in), I2C (harness I2C), INT_BQ (out)

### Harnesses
I2C: SCL, SDA

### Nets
+1V8: 1V8.X C87.2 U12.5(OUT)
+3V3: C88.1 Q4.D Q4.D2 R71.2 R76.1 R87.2 U12.1(IN) U12.3(EN)
+3V3_DBG: 3V3_DBG.X C96.2 Q4.K Q4.K2 Q4.S
+3V3_PCIE: 3V3_PCIE.X 3V3_PCIE_1.X 3V3_PCIE_2.X C104.2 C106.2 C125.2 C126.2 L6.2 R64.2
+3V8: 3V8.X 3V8_2.X 3V8_3.X C85.2 C140.2 L5.2 R70.1 U11.15(SYS) U11.16(SYS)
+5V: 5V.X 5V_1.X 5V_2.X C83.2 C129.2 C148.2 C149.2 C150.2 C151.2 D10.2(C) U13.4(PVIN) U13.5(PVIN) U13.6(VIN) U24.6(OUT) U25.6(OUT)
+5V_BQ: C64.2 R123.2 U11.23(PMID) U25.5(IN)
+5V_DBG: 5V_DBG.X C97.1 U14.1(IN) U14.3(EN)
+5V_MPM: C61.2 C62.2 C92.2 C144.2 C145.2 C146.2 R88.2 R120.2 U6.5(VOUT) U11.1(VBUS) U11.24(VBUS) U24.5(IN)
GND: BAT_GND.X C34.1 C61.1 C62.1 C64.1 C65.1 C82.1 C83.1 C85.1 C86.2 C87.1 C88.2 C92.1 C96.1 C97.2 C104.1 C106.1 C117.1 C121.1 C122.1 C123.1 C124.1 C125.1 C126.1 C127.2 C129.1 C140.1 C144.1 C145.1 C146.1 C147.1 C148.1 C149.1 C150.1 C151.1 D10.1(A) GND_3V8_1.X GND_3V8_2.X GND_3V8_3.X J18.1(-) J18.2(GND) PWR_GND1.X PWR_GND2.X PWR_GND3.X R50.1 R66.1 R67.1 R72.2 R74.1 R75.1 R77.1 R89.2 R121.1 R122.1 R124.1 U6.GND U11.17(PGND) U11.18(PGND) U11.EXP(TH) U12.2(GND) U13.2(GND) U13.3(GND) U13.15(EP) U14.2(GND) U24.2(OVLO) U24.8(GND) U24.9(IMON) U25.8(GND) U25.9(IMON) X1.2
CE_bq: R74.2 U11.9(C~{E})  [project net CE_bq_12]
I2C0.SCL: U11.5(SCL) ; port I2C.SCL
I2C0.SDA: U11.6(SDA) ; port I2C.SDA
ILIM_bq: R72.1 U11.10(ILIM)  [project net ILIM_bq_12]
INT_bq: INT_BQ.X R76.2 U11.7(INT) ; port INT_BQ  [project net GPIO.6]
PWM.6: R69.1 ; port EN_3V3_PCIE
PWR_IN: C116.2 C118.2 C119.2 C120.2 L3.1 PWR_IN.X PWR_IN_1.X PWR_IN_2.X R111.1 X1.1  [project net PWR_IN_12]
REGN: C86.1 R73.2 U11.22(REGN)  [project net REGN_12]
STAT: R71.1 U11.4(STAT)  [project net STAT_12]
SW_bq: C84.2 L5.1 U11.19(SW) U11.20(SW)  [project net SW_bq_12]
TS_bq: R73.1 R75.2 U11.11(TS1) U11.12(TS2)  [project net TS_bq_12]
VBAT: BAT.X J16.1(-) J16.2(GND) U11.13(BAT) U11.14(BAT)  [project net VBAT_12]
NetC34_2: C34.2 R65.2 U13.8(COMP)
NetC65_2: C65.2 U24.7(DVDT)
NetC82_2: C82.2 R65.1
NetC84_1: C84.1 U11.21(BTST)
NetC93_1: C93.1 U13.13(BOOT)
NetC93_2: C93.2 L6.1 U13.11(PH) U13.12(PH)
NetC116_1: C116.1 C121.2
NetC117_2: C117.2 Q4.A Q4.G R89.1 U14.5(OUT)
NetC118_1: C118.1 C122.2
NetC119_1: C119.1 C123.2
NetC120_1: C120.1 C124.2
NetC127_1: C127.1 U13.9(SS/TR)
NetC128_1: C128.1 R67.2 R68.1 U13.7(VSENSE)
NetC128_2: C128.2 R64.1 R68.2
NetC147_2: C147.2 U25.7(DVDT)
NetL3_2: L3.2 U6.8(VIN)
NetR50_2: R50.2 U6.4(FB)
NetR66_2: R66.2 U13.1(RT/CLK)
NetR69_2: R69.2 R87.1 U13.10(EN)
NetR70_2: R70.2 U11.8(OTG)
NetR77_2: R77.2 U6.2(RFREQ)
NetR88_1: R88.1 R122.2 U25.2(OVLO)
NetR111_2: R111.2 U6.1(EN)
NetR120_1: R120.1 R121.2 U24.1(EN/UVLO) U24.4(PGTH)
NetR123_1: R123.1 R124.2 U25.1(EN/UVLO) U25.4(PGTH)

Not connected (* = marked no-connect by the designer): U6 3(PGOOD)*; U11 2(D+)* 3(D-)*; U12 4(NC)*; U13 14(PWRGD)*; U14 4(NC)*; U24 3(PG)* 10(DNC)*; U25 3(PG)* 10(DNC)*; X1 3*

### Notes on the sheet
- Power in from jack, +5V step down
- Power OR between +5V from jack or battery boost
- Inductor as EMI filter
- When +5V_MPM gets above 4.5V the voltage on U24 PGTH pin raises over 1.223V and therefore U24 switches ON.
- Slew rate from MPM = 2000/1nF = 2V/ms
  Slew rate from BQ = 2000/150pF = 13.3V/ms
- Battery charger and +5V boost from battery
- When +5V_MPM drops below 4.71V the voltage on the U25 OVLO pin drops below 1.07V and therefore U25 switches ON.
- Audio 1V8 linear regulator
- PCIE dedicated high current 3V3
- (near R89) Dedicated Debugger PWR
- (near R69) EN has internal pullup.
- (near 5V_DBG) +5V_DBG coming from micro usb J10

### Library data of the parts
1V8 3V3_DBG 3V3_PCIE 3V3_PCIE_1 3V3_PCIE_2 3V8 3V8_2 3V8_3 5V 5V_1 5V_2 BAT BAT_GND GND_3V8_1-GND_3V8_3 INT_BQ PWR_GND1-PWR_GND3 PWR_IN PWR_IN_1 PWR_IN_2 = UT0013-A.2: Test point 1.00mm
5V_DBG = UT0013-A.1: Test point 1.00mm
C34 C82 C127 = C0009-A.9: CAP CHIP 0402 10nF 50V X7R 10%; Manufacturer: KEMET; Code Arduino: 0165
C61 C62 C144-C146 C148-C151 = C0062-A.9: CAP CHIP 1206 100UF 10V X5R 20%; Manufacturer: Samsung; Code Arduino: A5503
C64 = C0116-A.1: CAP CHIP 1206 68UF 10V X5R 20%; Manufacturer: TDK; Code Arduino: C0116
C65 = C0007-A.9: CAP CHIP 0402 1nF 50V X7R 10%; Manufacturer: KEMET; Code Arduino: 2321
C83 C116 C118-C124 C129 = C0111-A.2: CAP CHIP 0805 22uF 25V X5R 20%; Manufacturer: Samsung Electro-Mechanics; Code Arduino: C0111
C84 = C0036-A.9: CAP CHIP 0402 47nF 50V X5R 10%; Manufacturer: Murata; Code Arduino: 2216
C85 C140 = C0098-A.5: CAP CHIP 0603 47UF X5R 20%; Manufacturer: Murata; Voltage Rating: 6.3V; Code Arduino: C0098
C86 = C0037-A.9: CAP CHIP 0402 4.7uF 6V3 X5R 20%; Manufacturer: Murata; Code Arduino: 0833; Voltage: 6.3V
C87 C88 C96 C97 = C0017-A.9: CAP CHIP 0402 1uF 10V X5R 10%; Manufacturer: KEMET; Code Arduino: 0133
C92 = C0047-A.12: CAP CHIP 0603 10uF 25V X5R 20%; Manufacturer: Murata; Part Number: C1608X5R1A226MT000N; Code Arduino: 2213
C93 = C0012-A.9: as C19 on sheet TOP
C104 C106 C125 C126 = C0098-A.5: CAP CHIP 0603 47UF X5R 20%; Manufacturer: Murata; Code Arduino: C0098
C117 = C0031-A.9: CAP CHIP 0402 2.2uF 6.3V X5R 10%; Manufacturer: Murata; Code Arduino: A5529
C128 C147 = C0074-A.7: CAP CHIP 0402 150PF 50V C0G 1%; Manufacturer: Murata; Code Arduino: C0074
D10 = D0031-A.3: DIODE TVS 5V 19V SOD323; Manufacturer: Nexperia; Code Arduino: D0031
J16 J18 = J0053-A.5: CONN BATTERY HOLDER 18650 CLIP SMT; Manufacturer: Keystone Electronics; Code Arduino: J0053
L3 L5 = I0017-A.6: IND FIXED 2.2UH 4A 61 MOHM SMD; Manufacturer: Bourns; Code Arduino: 2218
L6 = I0049-A.3: IND FIXED SMD 3.3UH 3.5A 76 mOHM; Manufacturer: Bourns; DC Resistance (DCR): 76mR; Tolerance: 20%; Test Frequency: 100kHz; Current: 4A; Code Arduino: I0049
Q4 = T0010-A.6: MOSFET P-CH 30V 4,5A 65mR SC70-6; Manufacturer: Vishay; Device Type: Mosfet P-CH SMD; Code Arduino: 2220
R50 R120 R123 = R0043-A.4: RES CHIP 0402 14K3 1/16W 1%; Manufacturer: Vishay; Power: 63mW; Code Arduino: R0043
R64 = R0046-A.7: RES CHIP 0402 49R9 1% 1/16W; Manufacturer: Vishay; Working Voltage: 50V; Power Rating: 100mW; Power: 63mW; Temperature Coefficient: 100ppm/°C; Resistance: 49.9R; Code Arduino: A5282
R65 = R0172-A.6: RES CHIP 0402 34K OHM 1% 1/16W; Manufacturer: Yageo; Code Arduino: R0172; Voltage Rating: 50V; Power Rating: 62.5mW; Resistance: 34kR; Max Power Dissipation: 63mW; Temperature Coefficient: 100ppm/°C
R66 = R0037-A.6: RES CHIP 0402 75K 1% 1/16W; Manufacturer: Yageo; Tolerance: 5%; Code Arduino: A5480; Power: 63mW
R67 = R0020-A.5: RES CHIP 0402 3K3 1% 1/16W; Manufacturer: Yageo; Code Arduino: 2232; Power: 63mW
R68 R122 = R0003-A.5: RES CHIP 0402 10K 1% 1/16W; Manufacturer: Vishay; Power: 63mW; Code Arduino: 0136
R69 = R0000-A.5: as R60 on sheet TOP
R70 R71 R74-R76 R89 = R0003-A.5: RES CHIP 0402 10K 1% 1/16W; Manufacturer: Vishay; Code Arduino: 0136; Power: 63mW
R72 = R0031-A.6: RES CHIP 0402 100R 1% 1/16W; Manufacturer: Vishay; Code Arduino: A5343; Power: 63mW
R73 = R0014-A.5: RES CHIP 0402 5K49 1% 1/16W; Manufacturer: Vishay; Code Arduino: 2197; Power: 63mW
R77 R87 R111 = R0001-A.5: as R57 on sheet TOP
R88 = R0172-A.6: RES CHIP 0402 34K OHM 1% 1/16W; Manufacturer: Yageo; Code Arduino: R0172; Power Rating: 62.5mW; Temperature Coefficient: 100ppm/°C; Resistance: 34kR; Voltage Rating: 50V; Max Power Dissipation: 63mW
R121 R124 = R0014-A.5: RES CHIP 0402 5K49 1% 1/16W; Manufacturer: Vishay; Power: 63mW; Code Arduino: 2197
U6 = U0050-A.6: IC DC/DC POWER MODULE 36V 5A LGA18; Manufacturer: MPS; Code Arduino: U0050
U11 = U0194-A.2: IC BATTERY CHARGER 4.5A VQFN24; Manufacturer: Texas Instruments; Code Arduino: U0194
U12 = U0110-A.3: IC V-REG LDO 1.8V 150mA  SOT25; Manufacturer: Diodes Inc; Number of Outputs: 1; Polarity: Positive; Power Dissipation: 640W; Min Input Voltage: 2V; Accuracy: 2%; Quiescent Current: 55uA; Max Power Dissipation: 640mW; Max Input Voltage: 6V; Output Type: Fixed; Code Arduino: U0110; Min Current Limit: 200mA
U13 = U0092-A.5: IC REG BUCK ADJ 6A SYNC 14VQFN; Manufacturer: Texas Instruments; Output Type: Adjustable; Min Input Voltage: 4.5V; Synchronous Rectifier: Yes; Output Voltage: 15V; Operating Supply Voltage: 17V; Number of Outputs: 1; Switching Frequency: 1.6MHz; Quiescent Current: 600uA; Min Output Voltage: 800mV; Code Arduino: U0092
U14 = U0027-A.6: IC V-REG LDO 3V3 600mA +En  SOT25; Manufacturer: Diodes Inc; Code Arduino: 2199
U24 U25 = U0192-A.2: IC IDEAL DIODE 2.3V-23V 5.5A QFN 2mm; Manufacturer: Texas Instruments; Max Supply Voltage: 28V; Code Arduino: U0192
X1 = J0083-A.5: CONN PWR JACK 2X5.5MM SOLDER; Manufacturer: CUI; Insulation Resistance: 50MR; Current Rating: 2.5A; Voltage Rating: 24V; Gender: Male; Shielding: Unshielded; Number of Conductors: 2; Code Arduino: J0083

## Sheet FIELDBUS.SchDoc: FIELDBUS
size A4; Author: Arturo Guadalupi; CompanyName: Arduino srl; DocumentNumber: ABX00043; Revision: V3.10; SheetNumber: 13; SheetTotal: 14; RevAuthor: S. Navaretti
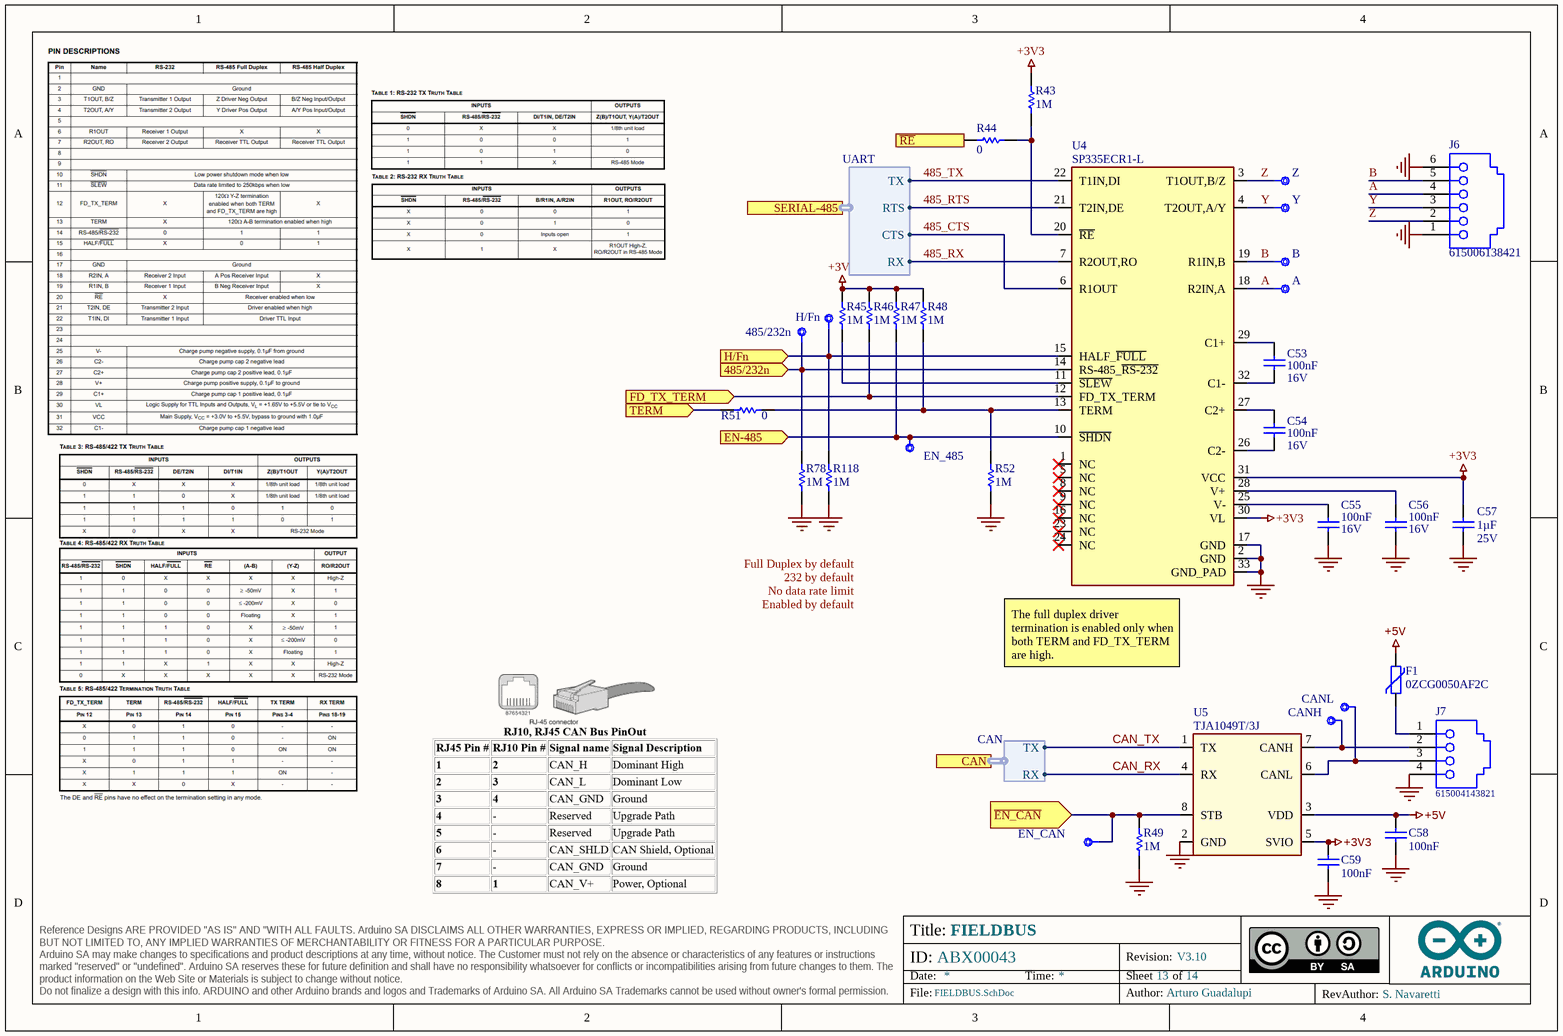
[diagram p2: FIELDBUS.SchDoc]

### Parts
485/232n  CMP-018-0005-A.3  [TP-1.00MM]  (value not drawn)  (no BOM)
A  CMP-018-0005-A.3  [TP-1.00MM]  (value not drawn)  (no BOM)
B  CMP-018-0005-A.3  [TP-1.00MM]  (value not drawn)  (no BOM)
C53  value 100nF  Voltage: 16V  [CAP-0402]  (hidden comment: C0402C104K4RACTU)
C54  value 100nF  Voltage: 16V  [CAP-0402]  (hidden comment: C0402C104K4RACTU)
C55  value 100nF  Voltage: 16V  [CAP-0402]  (hidden comment: C0402C104K4RACTU)
C56  value 100nF  Voltage: 16V  [CAP-0402]  (hidden comment: C0402C104K4RACTU)
C57  value 1µF  Voltage: 25V  [CAP-0603]  (hidden comment: C0603C105K3PACTU)
C58  value 100nF  [CAP-0402]  (hidden comment: C0402C104K4RACTU)
C59  value 100nF  [CAP-0402]  (hidden comment: C0402C104K4RACTU)
CANH  CMP-018-0005-A.3  [TP-1.00MM]  (value not drawn)  (no BOM)
CANL  CMP-018-0005-A.3  [TP-1.00MM]  (value not drawn)  (no BOM)
EN_485  CMP-018-0005-A.3  [TP-1.00MM]  (value not drawn)  (no BOM)
EN_CAN  CMP-018-0005-A.3  [TP-1.00MM]  (value not drawn)  (no BOM)
F1  0ZCG0050AF2C  [1812]
H/Fn  CMP-018-0005-A.3  [TP-1.00MM]  (value not drawn)  (no BOM)
J6  615006138421  [615006138421]
J7  615004143821  [615004143821]
R43  value 1M  [RES-0402]  (hidden comment: CRCW04021M00FKED)
R44  value 0  [RES-0402]  (hidden comment: CRCW04020000Z0EDC)
R45  value 1M  [RES-0402]  (hidden comment: CRCW04021M00FKED)
R46  value 1M  [RES-0402]  (hidden comment: CRCW04021M00FKED)
R47  value 1M  [RES-0402]  (hidden comment: CRCW04021M00FKED)
R48  value 1M  [RES-0402]  (hidden comment: CRCW04021M00FKED)
R49  value 1M  [RES-0402]  (hidden comment: CRCW04021M00FKED)
R51  value 0  [RES-0402]  (hidden comment: CRCW04020000Z0EDC)
R52  value 1M  [RES-0402]  (hidden comment: CRCW04021M00FKED)
R78  value 1M  [RES-0402]  (hidden comment: CRCW04021M00FKED)
R118  value 1M  [RES-0402]  (hidden comment: CRCW04021M00FKED)
U4  SP335ECR1-L  [QFN50P500X500X100_HS-33N]
U5  TJA1049T/3J  [TJA1049T_3J-Footprint-1]
Y  CMP-018-0005-A.3  [TP-1.00MM]  (value not drawn)  (no BOM)
Z  CMP-018-0005-A.3  [TP-1.00MM]  (value not drawn)  (no BOM)

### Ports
485/232n (in), CAN (harness CAN), EN-485 (in), FD_TX_TERM (in), H/Fn (in), SERIAL-485 (harness UART), TERM (in), ~{EN_CAN} (in), ~{RE} (in)

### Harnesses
CAN: RX, TX
UART: CTS, RTS, RX, TX

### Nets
+3V3: C57.2 C59.2 R43.2 R45.2 R46.2 R47.2 R48.2 U4.30(VL) U4.31(VCC) U5.5(SVIO)
+5V: C58.1 F1.2 U5.3(VDD)
GND: C55.2 C56.2 C57.1 C58.2 C59.1 J6.1 J6.6 J7.4 R49.2 R52.1 R78.1 R118.1 U4.2(GND) U4.17(GND) U4.33(GND_PAD) U5.2(GND)
485/232n: 485/232n.X R78.2 U4.14(RS-485_~{RS-232}) ; port 485/232n
485_CTS: U4.6(R1OUT) ; port SERIAL-485.CTS  [project net SERIAL0.CTS]
485_RTS: U4.21(T2IN,DE) ; port SERIAL-485.RTS  [project net SERIAL0.RTS]
485_RX: U4.7(R2OUT,RO) ; port SERIAL-485.RX  [project net SERIAL0.RX]
485_TX: U4.22(T1IN,DI) ; port SERIAL-485.TX  [project net SERIAL0.TX]
A: A.X J6.4 U4.18(R2IN,A)  [project net A_13]
B: B.X J6.5 U4.19(R1IN,B)  [project net B_13]
CAN_RX: U5.4(RX) ; port CAN.RX  [project net CAN1.RX]
CAN_TX: U5.1(TX) ; port CAN.TX  [project net CAN1.TX]
~{EN_CAN}: EN_CAN.X R49.1 U5.8(STB) ; port ~{EN_CAN}
EN_485: EN_485.X R47.1 U4.10(~{SHDN}) ; port EN-485
FD_TX_TERM: R46.1 U4.12(FD_TX_TERM) ; port FD_TX_TERM
H/Fn: H/Fn.X R118.2 U4.15(HALF_~{FULL}) ; port H/Fn
PWM.7: R51.1 ; port TERM
PWM.8: R44.1 ; port ~{RE}
Y: J6.3 U4.4(T2OUT,A/Y) Y.X  [project net Y_13]
Z: J6.2 U4.3(T1OUT,B/Z) Z.X  [project net Z_13]
NetC53_1: C53.1 U4.29(C1+)
NetC53_2: C53.2 U4.32(C1-)
NetC54_1: C54.1 U4.27(C2+)
NetC54_2: C54.2 U4.26(C2-)
NetC55_1: C55.1 U4.25(V-)
NetC56_1: C56.1 U4.28(V+)
NetCANH_X: CANH.X J7.2 U5.7(CANH)
NetCANL_X: CANL.X J7.3 U5.6(CANL)
NetF1_1: F1.1 J7.1
NetR43_1: R43.1 R44.2 U4.20(~{RE})
NetR45_1: R45.1 U4.11(~{SLEW})
NetR48_1: R48.1 R51.2 R52.2 U4.13(TERM)

Not connected (* = marked no-connect by the designer): U4 1(NC)* 5(NC)* 8(NC)* 9(NC)* 16(NC)* 23(NC)* 24(NC)*

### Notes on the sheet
- Full Duplex by default
- 232 by default
- No data rate limit
- Enabled by default
- (near U4) The full duplex driver termination is enabled only when both TERM and FD_TX_TERM are high.

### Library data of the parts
485/232n A B CANH CANL EN_485 EN_CAN H/Fn Y Z = UT0013-A.2: Test point 1.00mm
C53-C56 C58 C59 = C0012-A.9: as C19 on sheet TOP
C57 = C0044-A.4: CAP CHIP 0603 1uF 25V X5R 10%; Manufacturer: KEMET; Code Arduino: 0006
F1 = P0009-2: PTC SMD 30V 500MA 1812; Manufacturer: Bel; Time to Trip: 0.15s; Code Arduino: P0009; Max Current Rating: 100A; Trip Current: 1A
J6 = J0086-A.3: CONN MOD JACK 6P6C R/A UNSHLD; Manufacturer: Wurth Electronics; Current Rating: 1.5A; Number of Positions: 6; Direction: Up; Connector Type: Jack,Socket; Mating Cycles: 500; Number of Ports: 1; Voltage Rating (AC): 120V; Shielding: Unshielded; Code Arduino: J0086; Insulation Resistance: 500MR; Gender: Female
J7 = J0085-A.3: CONN MOD JACK 4P4C R/A UNSHLD; Manufacturer: Wurth Electronics; Direction: Up; Code Arduino: J0085; Number of Ports: 1; Shielding: Unshielded
R43 R45-R49 R52 R78 R118 = R0058-A.5: RES CHIP 0402 1M 1% 1/16W; Manufacturer: Vishay; Power: 63mW; Code Arduino: 0139
R44 R51 = R0000-A.5: as R60 on sheet TOP
U4 = U0145-A.2: Line Transceiver, 2 Func, 2 Driver, 2 Rcvr; Manufacturer: MaxLinear; Code Arduino: U0145
U5 = U0114-A.4: IC CAN TRANSCEIVER 1Mbps STBY 5.25V SOIC8; Manufacturer: NXP; Code Arduino: U0114; Data Rate: 5Mbps; Number of Transceivers: 1; Simplex/Duplex: Half Duplex; Receiver Hysteresis: 300mV; Min Supply Voltage: 4.75V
